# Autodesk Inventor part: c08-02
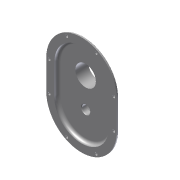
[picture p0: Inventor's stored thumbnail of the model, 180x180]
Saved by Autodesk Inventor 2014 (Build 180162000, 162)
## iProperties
Created: 2010-12
Part Number: c08-02
Document SubType Name: Modeling
Designer: Thom Tremblay
Density: 7.25 g/cm^3
Material: Iron, Cast
Mass: 515.624 g
Surface Area: 438.513 cm^2
Volume: 71.1205 cm^3
Appearance: Steel
Author: Thom Tremblay
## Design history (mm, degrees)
sketch "Sketch1"
  geometry: L1 (-50, -50)-(-50, 0); L2 (50, 0)-(50, -50); L3 (-60, 0)-(-60, -50); L4 (60, -50)-(60, 0); A1 r 50 centre (0, 0) between (50, 0) and (-50, 0); A2 r 50 centre (0, -50) between (-50, -50) and (50, -50); A3 r 60 centre (0, -50) between (-60, -50) and (60, -50); A4 r 60 centre (0, 0) between (60, 0) and (-60, 0); 1 further point
  constraints: 8 end point, 8 point on circle, 4 centre point, 4 tangent, 2 parallel, 1 coincident, 1 vertical, 3 other
  dimensions: "d0" = 50 distance of L2.start L2.end; "d1" = 50 radius of A1; "d2" = 10 radial gap between concentric circles of A4 A1
extrude "Extrusion1" new body sketch "Sketch1" distance "d3" = 10; taper "d4" = -2 deg
extrude "Extrusion2" join sketch "Sketch1" distance "d5" = 3; taper "d6" = -2 deg
fillet "Fillet1" dims "d7" = 8
shell "Shell2" dims "d128" = 3
fillet "Fillet2" dims "d9" = 1.5, "d10" = 1
sketch "Sketch7"
  geometry: C1 r 22.5 at (0, 0); 1 further point
  constraints: 1 centre point, 1 coincident
  dimensions: "d63" = 45 diameter of C1
extrude "Extrusion8" join sketch "Sketch7" distance "d64" = 19; taper "d65" = -2 deg
hole "Hole3" diameter "d68" = 35; stored, may be unused: countersink angle "d72" = 82 deg, drill point angle "d74" = 118 deg; dims "d66" = 10, "d67" = 10, "d69" = 19.05, "d70" = 9.525, "d71" = 6.35, "d73" = 25.4
fillet "Fillet11" dims "d75" = 3
sketch "Sketch8"
  geometry: C1 r 12.5 at (0, -50); A1 r 60 centre (0, -50) between (-60, -50) and (60, -50) reference; 1 further point
  constraints: 1 centre point, 1 coincident
  dimensions: "d76" = 25 diameter of C1
extrude "Extrusion9" join sketch "Sketch8" distance "d77" = 12; taper "d78" = -2 deg; dims "d89" = 8, "d90" = -2 deg
fillet "Fillet12" dims "d79" = 3
hole "Hole4" diameter "d82" = 14; stored, may be unused: countersink angle "d86" = 82 deg, drill point angle "d88" = 118 deg; dims "d80" = 10, "d81" = 10, "d83" = 19.05, "d84" = 9.525, "d85" = 6.35, "d87" = 8
sketch "Sketch9" dims "d91" = 45
  geometry: L1 (0, 0)-(0, 22.5); C1 r 4 at (0, 22.5); 1 further point
  constraints: 2 end point, 1 centre point, 1 coincident, 1 vertical, 1 vertical alignment, 2 other
  dimensions: "d92" = 8 diameter of C1
extrude "Extrusion10" join sketch "Sketch9" stored distance "d95" = 0; taper "d96" = 2 deg
fillet "Fillet13" dims "d97" = 3
hole "Hole5" diameter "d100" = 3.242; stored, may be unused: countersink angle "d104" = 82 deg, drill point angle "d106" = 118 deg; dims "d98" = 10, "d99" = 10, "d101" = 8, "d102" = 9.525, "d103" = 6.35, "d105" = 10
pattern_circular "Circular Pattern1" dims "d108" = 360 deg
sketch "Sketch10"
  geometry: L1 (-55, -50.8)-(-55, 0); L2 (55, 0)-(55, -50.8); A1 r 55 centre (0, 0) between (55, 0) and (-55, 0); A2 r 55 centre (0, -50.8) between (-55, -50.8) and (55, -50.8); 9 further points
  constraints: 8 point on circle, 5 coincident, 4 end point, 4 tangent, 2 centre point, 2 horizontal alignment, 2 vertical alignment, 1 parallel, 1 vertical
  dimensions: "d118" = 55 radius of A1; "d120" = 50 distance of point (25, 48.99) point (-25, 48.99)
hole "Hole7" sketch "Sketch10" at (-55, -50.8), (-55, 0), (-25, 48.99), (25, 48.99), (55, 0), (55, -50.8), (25, -99.79), (-25, -99.79) diameter "d121" = 4.5; stored, may be unused: countersink angle "d125" = 82 deg, drill point angle "d127" = 118 deg; dims "d122" = 19.05, "d123" = 7.0866, "d124" = 6.35, "d126" = 25.4
chamfer "Chamfer1" distance "d129" = 1; stored, may be unused: second distance "d130" = 2, angle "d131" = 45 deg
body "Solid1"
